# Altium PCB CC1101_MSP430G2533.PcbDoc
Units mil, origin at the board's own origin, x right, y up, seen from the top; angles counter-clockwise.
Board outline 6000 x 4000 mil, 2 copper layers (Top Layer, Bottom Layer); 37 components, 35 nets, 173 pads, 0 vias.
Unrouted connection lines stored in the file: 1.
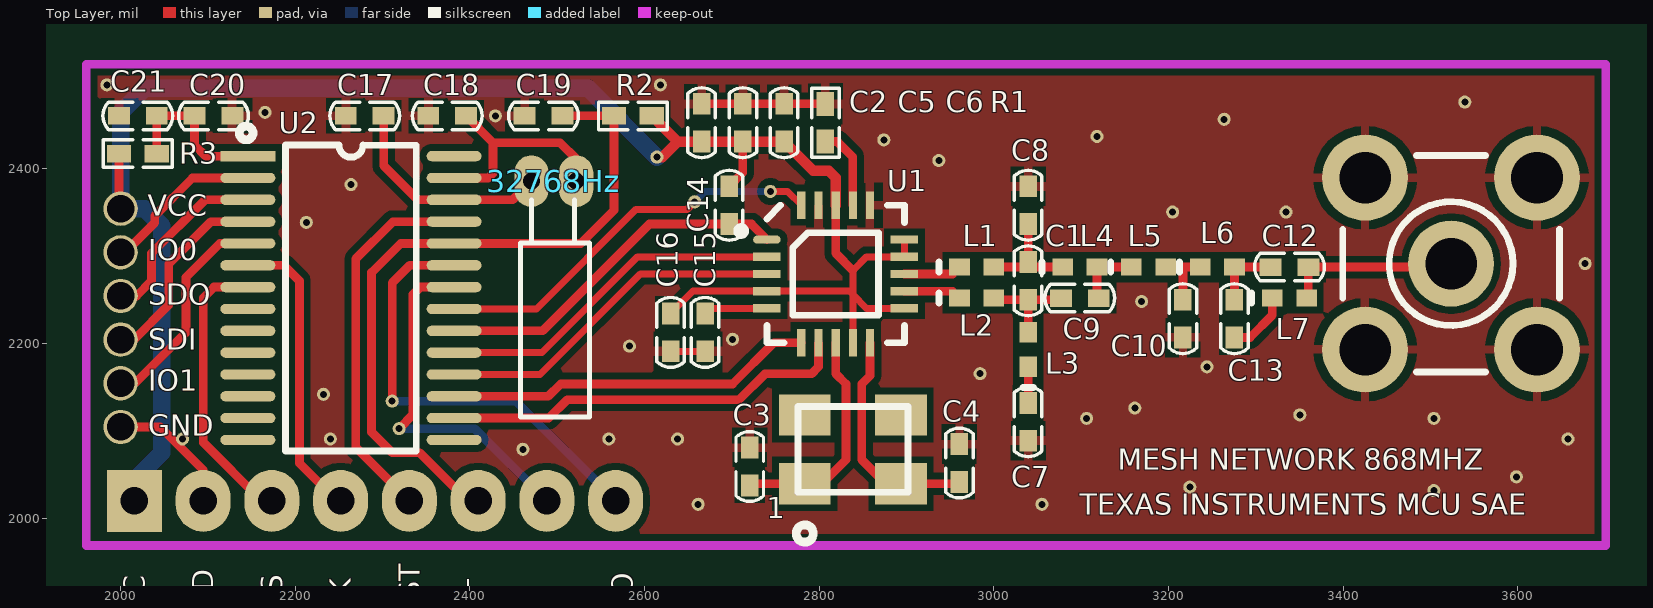
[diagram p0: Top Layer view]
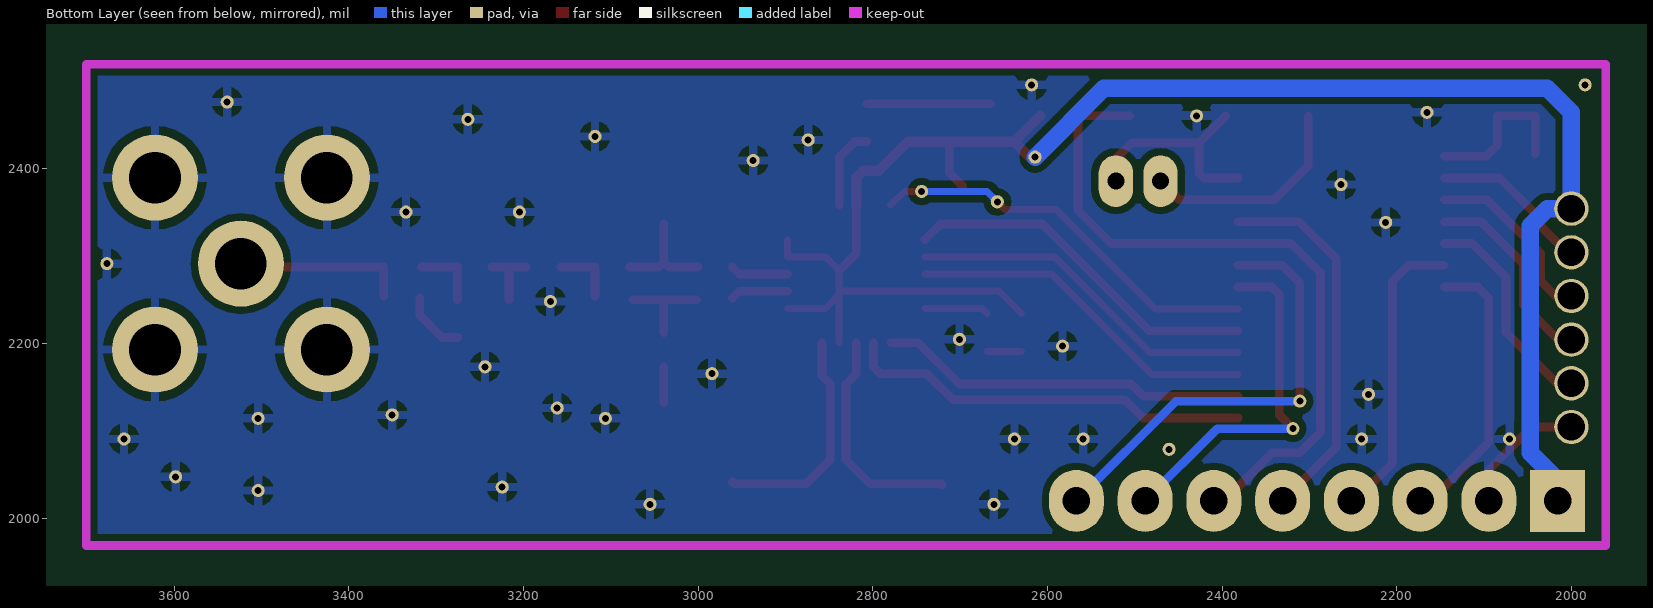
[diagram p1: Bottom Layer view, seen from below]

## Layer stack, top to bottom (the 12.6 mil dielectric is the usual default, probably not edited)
Top Solder: solder mask 0.4, Solder Resist, Dk 3.5
Top Layer: signal copper 1.4
Dielectric 1: dielectric 12.6, FR-4, Dk 4.8
Bottom Layer: signal copper 1.4
Bottom Solder: solder mask 0.4, Solder Resist, Dk 3.5

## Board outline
1000,1000 7000,1000 7000,5000 1000,5000

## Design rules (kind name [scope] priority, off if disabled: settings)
Clearance [All] p1: gap=8
ComponentClearance [All] p1 off: gap=10 collisioncheckmode=3 verticalgap=10 showdistances=FALSE
PolygonConnect [All] p1: connectstyle=Relief reliefconductorwidth=10 reliefentries=4 polygonreliefangle="90 Angle" airgapwidth=10
RoutingVias [All] p1: holewidth=28 width=50 viastyle="Through Hole" minholewidth=28 minwidth=50 maxholewidth=28 maxwidth=50
SolderMaskExpansion [All] p1: expansion=4
Width [All] p1: maxlimit=20 minlimit=8 preferedwidth=8
28 further rules are at their usual default settings.

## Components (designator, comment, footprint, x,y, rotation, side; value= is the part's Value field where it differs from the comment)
26MHz "X1" XIAL4P-SMT3*2X5 2838.58,2078.74 r0 top
32768Hz "X2" "XIAL-2*5V - noSMT" 2496.06,2385.83 r180 top
C1 "" C/0402 3039.37,2271.65 r90 top
C2 "" C/0402 2665.35,2452.76 r270 top
C3 "" C/0402 2720.47,2059.06 r270 top
C4 "" C/0402 2960.63,2062.99 r270 top
C5 "" C/0402 2712.6,2452.76 r270 top
C6 "" C/0402 2759.84,2452.76 r270 top
C7 "" C/0402 3039.37,2110.24 r90 top
C8 "" C/0402 3039.37,2358.27 r90 top
C9 "" C/0402 3098.43,2251.97 r180 top
C10 "" C/0402 3216.54,2228.35 r90 top
C12 "" C/0402 3338.58,2287.4 r180 top
C13 "" C/0402 3275.59,2228.35 r90 top
C14 "" C/0402 2696.85,2358.27 r90 top
C15 "" C/0402 2669.29,2212.6 r90 top
C16 "" C/0402 2629.92,2212.6 r90 top
C17 "" C/0402 2279.53,2460.63 r180 top
C18 "" C/0402 2374.02,2460.63 r180 top
C19 "" C/0402 2484.25,2460.63 r180 top
C20 "" C/0402 2106.3,2460.63 r180 top
C21 "" C/0402 2019.68,2460.63 r0 top
D1 "" Con6p_1mm 2000,2354.33 r270 top
J1 "ANT_CC1101" SMB_V-RJ45 3523.62,2291.34 r0 top
JTAG "" "CN8P-2.0 - NoBoard" 2291.34,2019.68 r0 top
L1 "" 0402-A 2980.31,2287.4 r0 top
L2 "" 0402-A 2980.31,2251.97 r0 top
L3 "" 0402-A 3039.37,2192.91 r90 top
L4 "" 0402-A 3098.43,2287.4 r0 top
L5 "" 0402-A 3177.17,2287.4 r0 top
L6 "" 0402-A 3255.91,2287.4 r0 top
L7 "" 0402-A 3338.58,2251.97 r0 top
R1 "" R/0402 2807.09,2452.76 r90 top
R2 "" R/0402 2586.61,2460.63 r0 top
R3 "" R/0402 2019.68,2417.32 r180 top
U1 "CC1101" IC-QFN20-RTJ4X4 2818.9,2279.53 r0 top
U2 "MSP430G2533" IC-SSOP28(DBQ) 2263.78,2251.97 r0 top

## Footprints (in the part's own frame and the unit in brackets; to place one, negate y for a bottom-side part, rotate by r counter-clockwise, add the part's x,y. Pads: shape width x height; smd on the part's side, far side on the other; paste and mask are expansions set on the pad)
0402-A [mm] "Chip Inductor, Body 1.0x0.5mm, IPC High Density"
  rect 0.6x0.5 smd: 1(-0.5,0) 2(0.5,0)
  silkscreen extent -1.1,-0.15 -1.1,0.15, body extent -0.55,-0.3 0.55,0.3, height 0.55
C/0402 [mil]
  rect 25x20 smd: 1(-21.65,0) 2(21.65,0)
  silkscreen extent -40,-16 40,16
"CN8P-2.0 - NoBoard" [mm]
  rect 1.6x1.8 hole 0.8: 1(-7,0)
  oval 1.6x1.8 hole 0.8: 2(-5,0) 3(-3,0) 4(-1,0) 5(1,0) 6(3,0) 7(5,0) 8(7,0)
Con6p_1mm [mm]
  round 1 hole 0.8: 1(0,0) 2(1.27,0) 3(2.54,0) 4(3.81,0) 5(5.08,0) 6(6.35,0)
IC-QFN20-RTJ4X4 [mm]
  oval 0.8x0.24 smd: 1(-2,1)
  rect 0.8x0.24 smd: 2(-2,0.5) 3(-2,0) 4(-2,-0.5) 5(-2,-1) 11(2,-1) 12(2,-0.5) 13(2,0) 14(2,0.5) 15(2,1)
  rect 0.24x0.8 smd: 6(-1,-2) 7(-0.5,-2) 8(0,-2) 9(0.5,-2) 10(1,-2) 16(1,2) 17(0.5,2) 18(0,2) 19(-0.5,2) 20(-1,2)
  silkscreen extent -2.85,-2 2,2
IC-SSOP28(DBQ) [mm]
  rect 1.6x0.3 smd: 1(-3,4.127)
  oval 1.6x0.3 smd: 2(-3,3.492) 3(-3,2.857) 4(-3,2.222) 5(-3,1.587) 6(-3,0.953) 7(-3,0.318) 8(-3,-0.318) 9(-3,-0.953) 10(-3,-1.587) 11(-3,-2.222) 12(-3,-2.857) 13(-3,-3.492) 14(-3,-4.127) 15(3,-4.127) 16(3,-3.492) 17(3,-2.857) 18(3,-2.222) 19(3,-1.587) 20(3,-0.953) 21(3,-0.318) 22(3,0.318) 23(3,0.953) 24(3,1.587) 25(3,2.222) 26(3,2.857) 27(3,3.492) 28(3,4.127)
  silkscreen extent -3.25,-4.45 1.9,5
R/0402 [mm]
  rect 0.7x0.508 smd: 1(-0.55,0) 2(0.55,0)
  silkscreen extent -1,-0.4 1,0.4
SMB_V-RJ45 [mm] "Connector; SMB Straight"
  round 2.5 hole 1.5: 1(0,0) 2(-2.5,-2.5) 2(-2.5,2.5) 2(2.5,-2.5) 2(2.5,2.5)
  silkscreen extent -3.15,-3.15 3.15,3.15
XIAL4P-SMT3*2X5 [mm]
  rect 1.5x1.2 smd: 1(-1.4,-1) 2(1.4,-1) 3(1.4,1) 4(-1.4,1)
  silkscreen extent -1.65,-2.7 1.6,1.25
"XIAL-2*5V - noSMT" [mm]
  oval 1x1.5 hole 0.5: 1(0.65,0) 2(-0.65,0)
  silkscreen extent -1.04,0.55 0.97,6.86

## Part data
26MHz 32768Hz: library part XTAL, "Crystal Oscillator"
C1 C2 C3 C4 C5 C6 C7 C8 C9 C10 C12 C13 C14 C15 C16 C17 C18 C19 C20 C21: library part Cap, "Capacitor"
D1: library part DIP6
JTAG: library part DIP8
L1 L2 L3 L4 L5 L6 L7: library part Inductor, "Inductor"
R1 R2 R3: library part Res1, "Resistor"

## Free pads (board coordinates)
  round 15 hole 8: 1(2311.02,2133.86) 3(2318.9,2102.36) 4(2614.17,2413.39) 5(2657.48,2362.2) 6(2744.09,2374.02) 7(3118.11,2437.01) 8(3263.78,2456.69) 9(3334.65,2350.39) 10(3539.37,2476.38) 11(3677.17,2291.34) 12(3657.48,2090.55) 13(3598.43,2047.24) 14(3503.94,2114.17) 15(3350.39,2118.11) 16(3161.42,2125.98) 17(3055.12,2015.75) 18(2984.25,2165.35) 19(2937.01,2409.45) 20(2637.8,2090.55) 21(2582.68,2196.85) 22(2700.79,2204.72) 23(2618.11,2496.06) 24(2874.02,2433.07) 25(2263.78,2381.89) 26(2429.13,2460.63) 27(2165.35,2464.57) 28(2212.6,2338.58) 29(2232.28,2141.73) 30(2240.16,2090.55) 31(2460.63,2078.74) 32(2559.06,2090.55) 33(2661.42,2015.75) 34(1984.25,2496.06) 35(2070.87,2090.55) 36(3224.41,2035.43) 37(3503.94,2031.5) 38(3204.72,2350.39) 39(3169.29,2248.03) 40(3244.09,2173.23) 42(3106.3,2114.17)

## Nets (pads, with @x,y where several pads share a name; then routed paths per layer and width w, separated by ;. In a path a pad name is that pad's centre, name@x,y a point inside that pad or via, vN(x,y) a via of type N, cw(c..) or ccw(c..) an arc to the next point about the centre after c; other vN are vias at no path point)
GND: C2.1 C3.1 C4.1 C5.1 C6.1 C7.1 C8.2 C10.1 C15.1 C16.1 C17.2 C18.2 C19.2 C20.1 C21.1 D1.6 J1.2 JTAG.2 pad.7 pad.8 pad.9 pad.10 pad.11 pad.12 pad.13 pad.14 pad.15 pad.16 pad.17 pad.18 pad.19 pad.20 pad.21 pad.22 pad.23 pad.24 pad.25 pad.26 pad.27 pad.28 pad.29 pad.30 pad.31 pad.32 pad.33 pad.34 pad.35 pad.36 pad.37 pad.38 pad.39 pad.40 pad.42 R1.2 U1.16 U1.19 | length 331.4
  Top Layer w8: C16.1 C15.1
  Top Layer w10: D1.6 2045.28,2104.33 2094.49,2055.12 JTAG.2 ; C2.1 C5.1 C6.1 R1.2
Net26MHz_1: 26MHz.1 C3.2 U1.8 | length 261.2
  Top Layer w10: C3.2 2722.44,2039.37 26MHz.1 2803.15,2039.37 2830.71,2066.93 2830.71,2153.54 2818.9,2165.35 U1.8
Net26MHz_2: 26MHz.2 C4.2 U1.10 | length 262
  Top Layer w10: U1.10 2858.27,2163.1 2848.71,2153.54 2848.71,2066.93 2876.27,2039.37 26MHz.2 2958.66,2039.37 C4.2
Net32768Hz_1: 32768Hz.1 C17.1 U2.26 | length 251.4
  Top Layer w10: C17.1 2301.18,2403.54 2340.26,2364.47 U2.26 2449.11,2364.47 32768Hz.1
Net32768Hz_2: 32768Hz.2 C18.1 U2.27 | length 253.7
  Top Layer w10: U2.27 2420.96,2389.47 2426.39,2394.89 2426.39,2429.91 ; C18.1 2426.39,2429.91 ; 32768Hz.2 2521.65,2411.42 2503.16,2429.91 2426.39,2429.91
NetC1_1: C1.1 C9.2 L2.2 L3.2 | length 110.2
  Top Layer w10: L2.2@3001.97,2250 C1.1 ; L3.2 C1.1 ; C9.2@3074.8,2250 C1.1
NetC1_2: C1.2 C8.1 L1.2 L4.1 | length 126.9
  Top Layer w10: L1.2 3033.46,2287.4 C1.2 ; C8.1 C1.2 ; L4.1 3045.28,2287.4 C1.2
NetC7_2: C7.2 L3.1 | length 41.3
  Top Layer w10: C7.2 L3.1
NetC9_1: C9.1 L4.2 L5.1 | length 72.8
  Top Layer w10: C9.1@3118.11,2253.94 L4.2 L5.1
NetC10_2: C10.2 L5.2 L6.1 | length 72.8
  Top Layer w10: L5.2 L6.1 ; C10.2 3216.54,2283.46
NetC12_1: C12.1 J1.1 L7.2 | length 198.5
  Top Layer w10: L7.2@3360.24,2253.94 C12.1 3519.68,2287.4 J1.1
NetC12_2: C12.2 C13.2 L6.2 | length 78.7
  Top Layer w10: C13.2 L6.2 C12.2
NetC13_1: C13.1 L7.1 | length 73.6
  Top Layer w10: C13.1 3293.31,2206.69 3318.9,2232.28 L7.1
NetC14_1: C14.1 U1.1 U2.20 | length 416.2
  Top Layer w10: U2.20 2483.37,2214.47 2605.52,2336.61 C14.1 2722.44,2336.61 U1.1
NetC15_2: C15.2 U1.5 | length 73.3
  Top Layer w8: C15.2 2675.2,2240.16 U1.5
NetC19_1: C19.1 JTAG.6 R2.1 U2.24 | length 811.8
  Top Layer w10: JTAG.6 2397.57,2019.68 2342.45,2074.8 2311.02,2074.8 2287.4,2098.43 2287.4,2281.21 2320.66,2314.47 U2.24 2527.07,2314.47 2564.96,2352.36 R2.1 C19.1
NetC20_2: C20.2 C21.2 R3.1 U2.1 | length 186.4
  Top Layer w10: R3.1 C21.2 C20.2 2084.65,2427.17 2097.34,2414.47 U2.1
NetD1_2: D1.2 U2.2 | length 188.3
  Top Layer w10: D1.2@2000,2307.09 D1.2 2005.12,2304.33 2039.01,2338.22 2039.01,2346.09 2082.38,2389.47 U2.2
NetD1_3: D1.3 U2.3 | length 209.7
  Top Layer w10: D1.3 2018.11,2254.33 2035.43,2271.65 2035.43,2303.15 2096.75,2364.47 U2.3
NetD1_4: D1.4 U2.4 | length 229.3
  Top Layer w10: D1.4 2015.35,2204.33 2055.12,2244.09 2055.12,2291.34 2103.25,2339.47 U2.4
NetD1_5: D1.5 U2.5 | length 248.9
  Top Layer w10: D1.5 2016.54,2154.33 2074.8,2212.6 2074.8,2275.59 2113.68,2314.47 U2.5
NetJTAG_3: JTAG.3 U2.7 | length 328.2
  Top Layer w10: U2.7 2106.99,2264.47 2094.49,2251.97 2094.49,2086.61 2161.42,2019.68 JTAG.3
NetJTAG_4: JTAG.4 U2.6 | length 340.3
  Top Layer w10: U2.6 2186.91,2289.47 2204.72,2271.65 2204.72,2062.99 2248.03,2019.68 JTAG.4
NetJTAG_5: JTAG.5 U2.25 | length 432.8
  Top Layer w10: JTAG.5 2269.4,2080.99 2269.4,2296.96 2311.91,2339.47 U2.25
NetJTAG_7: JTAG.7 pad.3 U2.22 | length 414.4
  Top Layer w10: pad.3 2334.65,2118.11 2334.65,2255.91 2343.21,2264.47 U2.22
  Bottom Layer w10: pad.3 2405.51,2102.36 JTAG.7
NetJTAG_8: JTAG.8 pad.1 U2.23 | length 517.9
  Top Layer w10: pad.1 2311.02,2269.4 2331.09,2289.47 U2.23
  Bottom Layer w10: pad.1 2452.76,2133.86 JTAG.8
NetL1_1: L1.1 U1.13 | length 66.3
  Top Layer w10: U1.13 2952.76,2279.53 L1.1
NetL2_1: L2.1 U1.12 | length 66.3
  Top Layer w10: U1.12 2952.76,2259.84 L2.1
NetR1_1: R1.1 U1.17 | length 94
  Top Layer w10: R1.1 2820.87,2431.1 2838.58,2413.39 U1.17
NetU1_2: U1.2 U2.19 | length 403.7
  Top Layer w8: U2.19 2482.42,2189.47 2592.16,2299.21 U1.2
NetU1_3: U1.3 U2.18 | length 405.9
  Top Layer w8: U2.18 2480.04,2164.47 2595.1,2279.53 U1.3
NetU1_6: U1.6 U2.17 | length 423
  Top Layer w10: U2.17 2489.86,2139.47 2503.94,2153.54 2700.79,2153.54 2748.03,2200.79 U1.6
NetU1_7: U1.7 U2.16 | length 469.2
  Top Layer w10: U2.16 2490.32,2114.47 2511.39,2135.54 2708.24,2135.54 2738.05,2165.35 2791.34,2165.35 2799.21,2173.23 U1.7
NetU1_20: pad.5 pad.6 U1.20 U2.21 | length 459.9
  Top Layer w8: U2.21 2476.11,2239.47 2590.25,2353.61 2648.89,2353.61 pad.5 ; pad.6 2763.78,2374.02 U1.20
  Bottom Layer w8: pad.5 2669.29,2374.02 pad.6
VCC: C2.2 C5.2 C6.2 C14.2 C16.2 D1.1 JTAG.1 pad.4 R2.2 R3.2 U1.4 U1.9 U1.11 U1.14 U1.15 U1.18 | length 2113.2
  Top Layer w8: C16.2 2629.92,2234.35 2655.41,2259.84 U1.4 2834.65,2259.84 2838.58,2255.91 ; U1.9 2838.58,2255.91 ; U1.11 2854.33,2240.16 2838.58,2255.91 ; U1.15 U1.14 2854.33,2299.21 2838.58,2283.46 2838.58,2255.91
  Top Layer w10: R3.2 1998.03,2356.3 D1.1 ; C14.2 2712.6,2395.67 C5.2 ; U1.18 2818.9,2303.15 2838.58,2283.46
  Top Layer w12: R2.2 2637.8,2431.1 ; pad.4 2620.08,2413.39 2637.8,2431.1 ; U1.18 2818.9,2389.76 2811.02,2397.64 2793.31,2397.64 C6.2 C5.2 C2.2 2637.8,2431.1
  Bottom Layer w20: JTAG.1 2015.75,2043.31 2047.24,2074.8 2047.24,2334.65 2027.56,2354.33 D1.1 2000,2464.57 2027.56,2492.13 2535.43,2492.13 pad.4
pads on no net: 26MHz.3 26MHz.4 U2.8 U2.9 U2.10 U2.11 U2.12 U2.13 U2.14 U2.15 U2.28

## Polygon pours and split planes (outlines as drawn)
GND on Top Layer "Top Layer- GND" (solid, remove dead copper, pour order 2): 1960.63,2519.68 3700.79,2519.68 3700.79,1968.5 1960.63,1968.5 1960.63,2519.68
GND on Bottom Layer "Top Layer- GND" (solid, remove dead copper, pour order 4): 1960.63,2519.68 3700.79,2519.68 3700.79,1968.5 1960.63,1968.5 1960.63,2519.68

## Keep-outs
Keep-Out Layer:
  lines w10: 1960.63,1968.5 3700.79,1968.5 3700.79,2519.68 1960.63,2519.68 1960.63,1968.5

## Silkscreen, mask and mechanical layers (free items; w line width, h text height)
Top Overlay:
  text "VCC" at 2031.13,2346.09 h23.62
  text "IO0" at 2031.5,2295.28 h23.62
  text "SDO" at 2031.5,2244.09 h23.62
  text "SDI" at 2031.5,2192.91 h23.62
  text "IO1" at 2031.5,2145.67 h23.62
  text "GND" at 2031.5,2094.49 h23.62
  text "MESH NETWORK 868MHZ" at 3141.73,2055.12 h23.62
  text "TEXAS INSTRUMENTS MCU SAE" at 3098.43,2003.94 h23.62
  text "VCC" at 2027.56,1866.14 h23.62 r90
  text "GND" at 2106.3,1866.14 h23.62 r90
  text "TMS" at 2185.04,1866.14 h23.62 r90
  text "TCK" at 2263.78,1866.14 h23.62 r90
  text "TEST" at 2342.52,1866.14 h23.62 r90
  text "RST" at 2421.26,1866.14 h23.62 r90
  text "TDI" at 2496.06,1866.14 h23.62 r90
  text "TDO" at 2586.61,1866.14 h23.62 r90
